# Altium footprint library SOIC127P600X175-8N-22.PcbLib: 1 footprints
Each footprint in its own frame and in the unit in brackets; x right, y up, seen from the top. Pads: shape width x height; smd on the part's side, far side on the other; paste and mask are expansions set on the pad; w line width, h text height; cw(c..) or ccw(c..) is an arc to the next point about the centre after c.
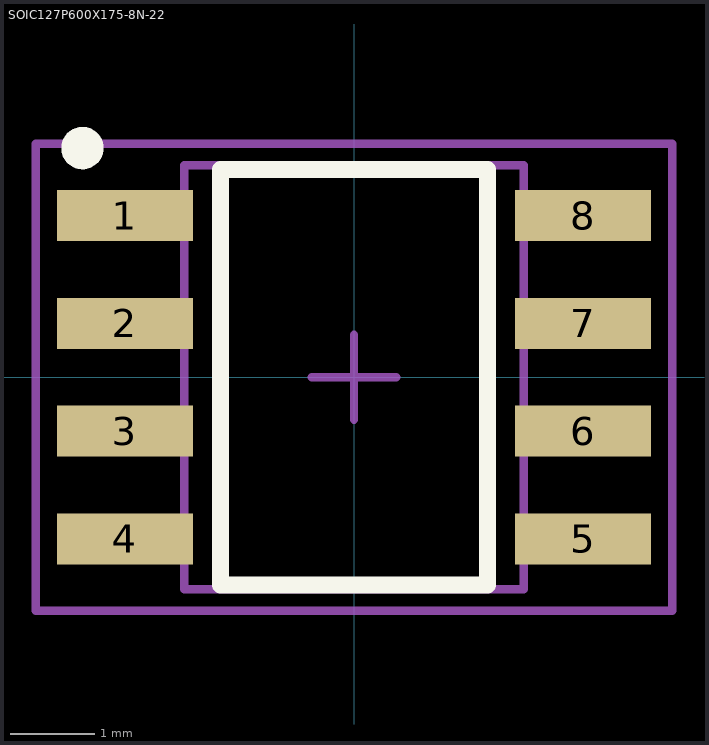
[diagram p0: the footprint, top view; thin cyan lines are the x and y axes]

## SOIC127P600X175-8N-22 [mm] "SOIC,1.27mm pitch;8 pin,3.90mm W X 4.90mm L X 1.75mm H body"
height 1.75
pads (8):
  rect 1.6x0.6 smd paste+0 mask+0: 1(-2.7,1.905) 2(-2.7,0.635) 3(-2.7,-0.635) 4(-2.7,-1.905) 5(2.7,-1.905) 6(2.7,-0.635) 7(2.7,0.635) 8(2.7,1.905)
Top Overlay:
  circle w0.25: c-3.2,2.7 r0.125
  lines w0.2: -1.575,-2.45 1.575,-2.45 1.575,2.45 -1.575,2.45 -1.575,-2.45
M3 (ASY_Text_Top):
  text ".DESIGNATOR" at 0,0 h1.2
M13 (CMP_Body_OTL_Top):
  lines w0.1: -2,-2.5 2,-2.5 2,2.5 -2,2.5 -2,-2.5
M15 (CMP_Courtyard_Top):
  lines w0.1: -0.5,0 0.5,0 ; 0,-0.5 0,0.5 ; -3.75,-2.75 3.75,-2.75 3.75,2.75 -3.75,2.75 -3.75,-2.75
3D body "PG-DSO-8-60_C66065-A5017-C013-03-0004.stp": height 1.74, standoff 0, extent -3,-2.465 3,2.465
